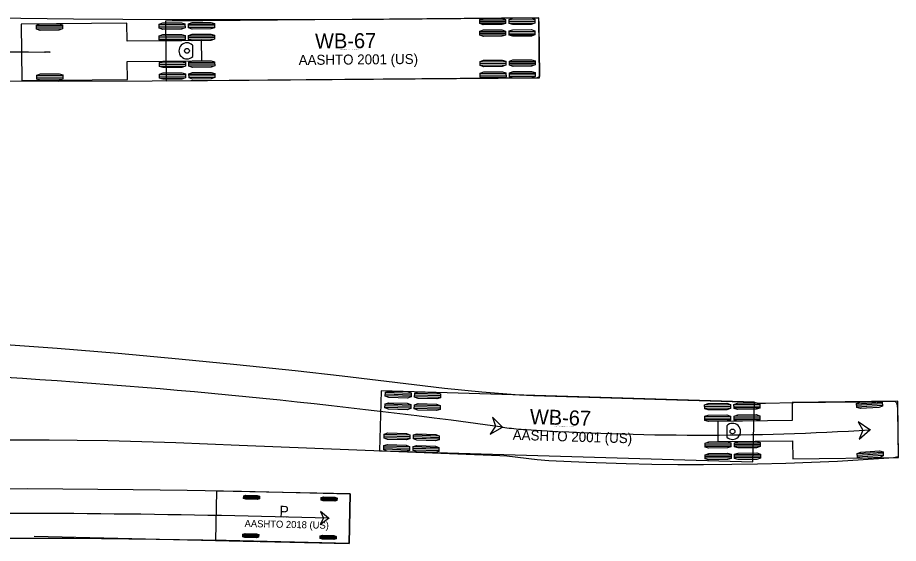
# Model space of a CAD drawing. Extents: x 2175591 to 2194071, y 76570 to 86955.
# Drawn here: x 2193090.5 to 2193215.5, y 86652.8 to 86727.4 of the extents above; entities that cross this region are included whole.
import ezdxf

# ---------------------------------------------------------------- set-up
doc = ezdxf.new("R2010")
doc.units = 0
doc.layers.add('C-UTIL-STRM-TEXT', color=7, linetype='Continuous')

msp = doc.modelspace()

# ---------------------------------------------------------------- linework, layer by layer
at = {"layer": 'C-UTIL-STRM-TEXT'}
for p, q in [((2193106.01, 86726.57), (2193091.01, 86726.44)), ((2193091.01, 86726.44), (2193091.08, 86718.44)), ((2193093.18, 86726.23), (2193096.85, 86726.26)), ((2193106.03, 86724), (2193106.01, 86726.57)), ((2193110.6, 86726.38), (2193114.26, 86726.41)), ((2193110.6, 86726.15), (2193114.26, 86726.18)), ((2193164.51, 86727.32), (2193111.51, 86726.86)), ((2193111.51, 86726.86), (2193111.58, 86718.37)), ((2193114.76, 86726.41), (2193118.43, 86726.44)), ((2193114.76, 86726.18), (2193118.43, 86726.22)), ((2193156.09, 86727.02), (2193159.76, 86727.05)), ((2193156.09, 86726.79), (2193159.76, 86726.82)), ((2193156.1, 86726.56), (2193159.76, 86726.59)), ((2193160.26, 86727.05), (2193163.92, 86727.08)), ((2193160.26, 86726.82), (2193163.93, 86726.85)), ((2193160.26, 86726.59), (2193163.93, 86726.63)), ((2193164.58, 86718.82), (2193164.51, 86727.32)), ((2193093.18, 86726), (2193096.85, 86726.03)), ((2193093.18, 86725.77), (2193096.85, 86725.8)), ((2193110.6, 86725.92), (2193114.27, 86725.95)), ((2193114.77, 86725.96), (2193118.43, 86725.99)), ((2193156.11, 86725.37), (2193159.77, 86725.4)), ((2193156.11, 86725.14), (2193159.77, 86725.17)), ((2193156.11, 86724.91), (2193159.78, 86724.94)), ((2193160.27, 86725.4), (2193163.94, 86725.43)), ((2193160.27, 86725.17), (2193163.94, 86725.2)), ((2193160.28, 86724.94), (2193163.94, 86724.98)), ((2193116.62, 86724.09), (2193106.03, 86724)), ((2193110.61, 86724.73), (2193114.28, 86724.76)), ((2193110.61, 86724.5), (2193114.28, 86724.53)), ((2193110.61, 86724.27), (2193114.28, 86724.3)), ((2193114.78, 86724.76), (2193118.44, 86724.79)), ((2193114.78, 86724.53), (2193118.44, 86724.57)), ((2193114.78, 86724.31), (2193118.45, 86724.34)), ((2193116.64, 86721.23), (2193116.62, 86724.09)), ((2193115.36, 86721.84), (2193115.35, 86723.46)), ((2193106.06, 86721.13), (2193116.64, 86721.23)), ((2193106.08, 86718.57), (2193106.06, 86721.13)), ((2193156.14, 86721.08), (2193159.81, 86721.11)), ((2193160.31, 86721.12), (2193163.98, 86721.15)), ((2193110.64, 86720.94), (2193114.31, 86720.98)), ((2193110.64, 86720.72), (2193114.31, 86720.75)), ((2193110.65, 86720.49), (2193114.31, 86720.52)), ((2193114.81, 86720.98), (2193118.47, 86721.01)), ((2193114.81, 86720.75), (2193118.48, 86720.78)), ((2193114.81, 86720.52), (2193118.48, 86720.55)), ((2193156.14, 86720.85), (2193159.81, 86720.89)), ((2193156.15, 86720.63), (2193159.81, 86720.66)), ((2193160.31, 86720.89), (2193163.98, 86720.92)), ((2193160.31, 86720.66), (2193163.98, 86720.69)), ((2193093.24, 86719.15), (2193096.91, 86719.18)), ((2193093.24, 86718.92), (2193096.91, 86718.95)), ((2193093.24, 86718.69), (2193096.91, 86718.72)), ((2193110.66, 86719.29), (2193114.32, 86719.33)), ((2193110.66, 86719.07), (2193114.32, 86719.1)), ((2193110.66, 86718.84), (2193114.33, 86718.87)), ((2193111.58, 86718.37), (2193164.58, 86718.82)), ((2193114.82, 86719.33), (2193118.49, 86719.36)), ((2193114.82, 86719.1), (2193118.49, 86719.13)), ((2193114.83, 86718.87), (2193118.49, 86718.9)), ((2193156.16, 86719.43), (2193159.82, 86719.46)), ((2193156.16, 86719.2), (2193159.82, 86719.24)), ((2193156.16, 86718.98), (2193159.83, 86719.01)), ((2193160.32, 86719.47), (2193163.99, 86719.5)), ((2193160.32, 86719.24), (2193163.99, 86719.27)), ((2193160.33, 86719.01), (2193163.99, 86719.04)), ((2193091.08, 86718.44), (2193106.08, 86718.57)), ((2193091.08, 86718.44), (2193091.08, 86718.44)), ((2193111.58, 86718.37), (2193111.58, 86718.37)), ((2193142.13, 86674.44), (2193141.88, 86665.94)), ((2193195.11, 86672.85), (2193142.13, 86674.44)), ((2193146.37, 86673.85), (2193142.7, 86673.96)), ((2193146.36, 86673.62), (2193142.7, 86673.73)), ((2193146.37, 86674.08), (2193142.71, 86674.19)), ((2193150.53, 86673.5), (2193146.86, 86673.61)), ((2193150.54, 86673.96), (2193146.87, 86674.07)), ((2193150.53, 86673.73), (2193146.87, 86673.84)), ((2193146.33, 86672.43), (2193142.66, 86672.54)), ((2193150.49, 86672.31), (2193146.83, 86672.42)), ((2193191.69, 86672.46), (2193188.02, 86672.42)), ((2193195.86, 86672.51), (2193192.19, 86672.47)), ((2193194.86, 86664.36), (2193195.11, 86672.85)), ((2193195.11, 86672.85), (2193195.11, 86672.85)), ((2193215.44, 86672.97), (2193200.44, 86672.79)), ((2193200.44, 86672.79), (2193200.47, 86670.23)), ((2193213.23, 86672.8), (2193209.57, 86672.57)), ((2193213.25, 86672.58), (2193209.59, 86672.35)), ((2193213.26, 86672.35), (2193209.6, 86672.12)), ((2193215.53, 86664.97), (2193215.44, 86672.97)), ((2193215.44, 86672.97), (2193215.44, 86672.97)), ((2193146.32, 86672.2), (2193142.65, 86672.31)), ((2193146.31, 86671.98), (2193142.65, 86672.08)), ((2193150.48, 86671.85), (2193146.81, 86671.96)), ((2193150.48, 86672.08), (2193146.82, 86672.19)), ((2193191.69, 86672.23), (2193188.03, 86672.19)), ((2193191.7, 86672), (2193188.03, 86671.96)), ((2193195.86, 86672.28), (2193192.19, 86672.24)), ((2193195.86, 86672.05), (2193192.2, 86672.01)), ((2193191.71, 86670.81), (2193188.04, 86670.77)), ((2193191.71, 86670.58), (2193188.05, 86670.54)), ((2193191.71, 86670.35), (2193188.05, 86670.31)), ((2193200.47, 86670.23), (2193189.88, 86670.1)), ((2193189.88, 86670.1), (2193189.92, 86667.24)), ((2193195.88, 86670.86), (2193192.21, 86670.82)), ((2193195.88, 86670.63), (2193192.21, 86670.59)), ((2193195.88, 86670.4), (2193192.21, 86670.36)), ((2193191.17, 86669.49), (2193191.19, 86667.88)), ((2193146.18, 86667.69), (2193142.52, 86667.8)), ((2193146.2, 86668.15), (2193142.53, 86668.26)), ((2193146.19, 86667.92), (2193142.53, 86668.03)), ((2193150.35, 86667.57), (2193146.68, 86667.68)), ((2193150.36, 86667.8), (2193146.69, 86667.91)), ((2193150.36, 86668.03), (2193146.7, 86668.14)), ((2193189.92, 86667.24), (2193200.5, 86667.36)), ((2193200.5, 86667.36), (2193200.53, 86664.79)), ((2193146.13, 86666.04), (2193142.47, 86666.15)), ((2193146.15, 86666.5), (2193142.48, 86666.61)), ((2193146.14, 86666.27), (2193142.48, 86666.38)), ((2193150.31, 86666.15), (2193146.64, 86666.26)), ((2193150.31, 86666.38), (2193146.65, 86666.49)), ((2193191.75, 86667.03), (2193188.09, 86666.99)), ((2193191.76, 86666.8), (2193188.09, 86666.76)), ((2193191.76, 86666.57), (2193188.09, 86666.53)), ((2193195.92, 86667.08), (2193192.25, 86667.03)), ((2193195.92, 86666.85), (2193192.26, 86666.81)), ((2193195.92, 86666.62), (2193192.26, 86666.58)), ((2193141.88, 86665.94), (2193194.86, 86664.36)), ((2193150.3, 86665.92), (2193146.63, 86666.03)), ((2193191.77, 86665.38), (2193188.11, 86665.34)), ((2193191.77, 86665.15), (2193188.11, 86665.11)), ((2193191.78, 86664.92), (2193188.11, 86664.88)), ((2193195.94, 86665.43), (2193192.27, 86665.38)), ((2193195.94, 86665.2), (2193192.27, 86665.16)), ((2193195.94, 86664.97), (2193192.28, 86664.93)), ((2193200.53, 86664.79), (2193215.53, 86664.97)), ((2193213.36, 86665.72), (2193209.7, 86665.5)), ((2193213.38, 86665.49), (2193209.72, 86665.27)), ((2193213.39, 86665.26), (2193209.73, 86665.04)), ((2193118.73, 86660.23), (2193118.57, 86653.23)), ((2193137.72, 86659.82), (2193118.73, 86660.23)), ((2193124.83, 86659.32), (2193122.58, 86659.36)), ((2193124.83, 86659.17), (2193122.58, 86659.22)), ((2193124.84, 86659.46), (2193122.59, 86659.51)), ((2193135.83, 86659.07), (2193133.58, 86659.13)), ((2193135.83, 86658.93), (2193133.58, 86658.99)), ((2193135.84, 86659.21), (2193133.59, 86659.27)), ((2193137.57, 86652.82), (2193137.72, 86659.82)), ((2193137.72, 86659.82), (2193137.72, 86659.82)), ((2193092.83, 86653.82), (2193124.51, 86653.08)), ((2193124.71, 86653.74), (2193122.46, 86653.79)), ((2193124.72, 86654.02), (2193122.47, 86654.07)), ((2193124.71, 86653.88), (2193122.47, 86653.93)), ((2193135.71, 86653.77), (2193133.46, 86653.84)), ((2193135.71, 86653.63), (2193133.46, 86653.7)), ((2193118.57, 86653.23), (2193137.57, 86652.82)), ((2193135.71, 86653.49), (2193133.46, 86653.56))]:
    msp.add_line(p, q, dxfattribs=at)
for points in [[(2193083.45, 86727.35), (2193098.45, 86727.16), (2193112.45, 86727.07), (2193127.11, 86727.07), (2193142.45, 86727.14), (2193164.44, 86727.32), (2193164.49, 86726.32), (2193164.52, 86722.99)], [(2193164.52, 86722.99), (2193164.56, 86718.99), (2193164.27, 86718.82), (2193109.61, 86718.35), (2193096.28, 86718.31), (2193085.95, 86718.36)], [(2193095.04, 86722.47), (2193094.71, 86722.47), (2193094.38, 86722.47)], [(2193088.15, 86681.05), (2193096.13, 86680.47), (2193104.76, 86679.77), (2193113.38, 86679), (2193121.64, 86678.19), (2193129.92, 86677.31), (2193136.55, 86676.56), (2193146.81, 86675.33), (2193151.11, 86674.84), (2193156.42, 86674.32), (2193161.73, 86673.87), (2193163.73, 86673.79), (2193195.04, 86672.85), (2193195.68, 86672.68), (2193196.68, 86672.68), (2193200.67, 86672.79), (2193209.67, 86672.9), (2193215.01, 86672.96), (2193215.25, 86672.73), (2193215.36, 86672.42), (2193215.41, 86671.75), (2193215.5, 86665.09), (2193214.85, 86664.94), (2193214.19, 86664.88), (2193210.53, 86664.64), (2193206.87, 86664.44), (2193203.21, 86664.28), (2193199.54, 86664.14), (2193195.55, 86664.04), (2193191.88, 86663.98), (2193187.88, 86663.96), (2193184.21, 86663.97), (2193180.55, 86664.01), (2193176.88, 86664.09), (2193171.22, 86664.29), (2193165.89, 86664.54), (2193164.23, 86664.68), (2193159.93, 86665.18), (2193158.93, 86665.24), (2193121.96, 86666.71), (2193112.97, 86667.05), (2193103.31, 86667.33), (2193098.97, 86667.41), (2193094.97, 86667.45), (2193089.31, 86667.43)], [(2193159.31, 86669.3), (2193157.9, 86670.72), (2193158.32, 86669.43), (2193157.57, 86668.31), (2193159.31, 86669.3)], [(2193211.48, 86668.92), (2193209.82, 86670.04), (2193210.48, 86668.86), (2193209.97, 86667.61), (2193211.48, 86668.92)], [(2193159.31, 86669.3), (2193159.64, 86669.25), (2193159.97, 86669.21), (2193160.3, 86669.17), (2193160.63, 86669.13), (2193160.96, 86669.09), (2193161.29, 86669.06), (2193161.62, 86669.03), (2193161.96, 86669), (2193162.29, 86668.98), (2193162.62, 86668.95)], [(2193075.89, 86660.56), (2193091.9, 86660.58), (2193106.91, 86660.47), (2193114.59, 86660.36), (2193122.26, 86660.21), (2193130.05, 86660.03), (2193137.71, 86659.82), (2193137.56, 86652.82), (2193120.11, 86653.2), (2193110.15, 86653.36), (2193098.52, 86653.49), (2193086.9, 86653.53)], [(2193134.65, 86656.38), (2193133.48, 86657.33), (2193133.9, 86656.4), (2193133.43, 86655.5), (2193134.65, 86656.38)]]:
    msp.add_lwpolyline(points, dxfattribs=at)
for points in [[(2193093.18, 86725.71), (2193093.18, 86726.29), (2193093.69, 86726.46), (2193096.33, 86726.49), (2193096.85, 86726.32), (2193096.85, 86725.75), (2193096.34, 86725.57), (2193093.7, 86725.55)], [(2193110.6, 86725.86), (2193110.59, 86726.43), (2193111.11, 86726.61), (2193113.75, 86726.63), (2193114.26, 86726.47), (2193114.27, 86725.89), (2193113.75, 86725.72), (2193111.11, 86725.69)], [(2193114.77, 86725.9), (2193114.76, 86726.47), (2193115.27, 86726.65), (2193117.91, 86726.67), (2193118.43, 86726.5), (2193118.43, 86725.93), (2193117.92, 86725.75), (2193115.28, 86725.73)], [(2193156.1, 86726.5), (2193156.09, 86727.07), (2193156.6, 86727.25), (2193159.24, 86727.27), (2193159.76, 86727.1), (2193159.76, 86726.53), (2193159.25, 86726.36), (2193156.61, 86726.33)], [(2193160.26, 86726.54), (2193160.26, 86727.11), (2193160.77, 86727.29), (2193163.41, 86727.31), (2193163.92, 86727.14), (2193163.93, 86726.57), (2193163.42, 86726.39), (2193160.78, 86726.37)], [(2193110.61, 86724.21), (2193110.61, 86724.78), (2193111.12, 86724.96), (2193113.76, 86724.98), (2193114.28, 86724.82), (2193114.28, 86724.24), (2193113.77, 86724.07), (2193111.13, 86724.04)], [(2193114.78, 86724.25), (2193114.78, 86724.82), (2193115.29, 86725), (2193117.93, 86725.02), (2193118.44, 86724.85), (2193118.45, 86724.28), (2193117.94, 86724.1), (2193115.3, 86724.08)], [(2193156.11, 86724.85), (2193156.11, 86725.42), (2193156.62, 86725.6), (2193159.26, 86725.62), (2193159.77, 86725.45), (2193159.78, 86724.88), (2193159.26, 86724.71), (2193156.62, 86724.68)], [(2193160.28, 86724.89), (2193160.27, 86725.46), (2193160.78, 86725.64), (2193163.42, 86725.66), (2193163.94, 86725.49), (2193163.94, 86724.92), (2193163.43, 86724.74), (2193160.79, 86724.72)], [(2193110.65, 86720.43), (2193110.64, 86721), (2193111.15, 86721.18), (2193113.79, 86721.2), (2193114.31, 86721.03), (2193114.31, 86720.46), (2193113.8, 86720.28), (2193111.16, 86720.26)], [(2193114.81, 86720.47), (2193114.81, 86721.04), (2193115.32, 86721.21), (2193117.96, 86721.24), (2193118.47, 86721.07), (2193118.48, 86720.5), (2193117.97, 86720.32), (2193115.33, 86720.3)], [(2193156.15, 86720.57), (2193156.14, 86721.14), (2193156.65, 86721.32), (2193159.29, 86721.34), (2193159.81, 86721.17), (2193159.81, 86720.6), (2193159.3, 86720.42), (2193156.66, 86720.4)], [(2193160.31, 86720.6), (2193160.31, 86721.18), (2193160.82, 86721.35), (2193163.46, 86721.38), (2193163.97, 86721.21), (2193163.98, 86720.64), (2193163.47, 86720.46), (2193160.83, 86720.44)], [(2193093.24, 86718.63), (2193093.24, 86719.2), (2193093.75, 86719.38), (2193096.39, 86719.4), (2193096.91, 86719.23), (2193096.91, 86718.66), (2193096.4, 86718.49), (2193093.76, 86718.46)], [(2193110.66, 86718.78), (2193110.66, 86719.35), (2193111.17, 86719.53), (2193113.81, 86719.55), (2193114.32, 86719.38), (2193114.33, 86718.81), (2193113.81, 86718.63), (2193111.18, 86718.61)], [(2193114.83, 86718.82), (2193114.82, 86719.39), (2193115.33, 86719.56), (2193117.97, 86719.59), (2193118.49, 86719.42), (2193118.49, 86718.85), (2193117.98, 86718.67), (2193115.34, 86718.65)], [(2193156.16, 86718.92), (2193156.16, 86719.49), (2193156.67, 86719.67), (2193159.31, 86719.69), (2193159.82, 86719.52), (2193159.83, 86718.95), (2193159.32, 86718.77), (2193156.68, 86718.75)], [(2193160.33, 86718.95), (2193160.32, 86719.53), (2193160.83, 86719.7), (2193163.47, 86719.73), (2193163.99, 86719.56), (2193163.99, 86718.99), (2193163.48, 86718.81), (2193160.84, 86718.79)], [(2193146.38, 86674.14), (2193146.36, 86673.57), (2193145.84, 86673.41), (2193143.2, 86673.49), (2193142.69, 86673.68), (2193142.71, 86674.25), (2193143.23, 86674.41), (2193145.87, 86674.33)], [(2193150.54, 86674.01), (2193150.52, 86673.44), (2193150.01, 86673.29), (2193147.37, 86673.36), (2193146.86, 86673.55), (2193146.88, 86674.12), (2193147.39, 86674.28), (2193150.03, 86674.2)], [(2193146.33, 86672.49), (2193146.31, 86671.92), (2193145.79, 86671.76), (2193143.15, 86671.84), (2193142.64, 86672.03), (2193142.66, 86672.6), (2193143.18, 86672.76), (2193145.82, 86672.68)], [(2193150.49, 86672.37), (2193150.47, 86671.79), (2193149.96, 86671.64), (2193147.32, 86671.72), (2193146.81, 86671.9), (2193146.83, 86672.48), (2193147.35, 86672.63), (2193149.98, 86672.55)], [(2193191.69, 86672.52), (2193191.7, 86671.95), (2193191.18, 86671.77), (2193188.55, 86671.74), (2193188.03, 86671.9), (2193188.02, 86672.48), (2193188.53, 86672.65), (2193191.17, 86672.69)], [(2193195.86, 86672.57), (2193195.86, 86672), (2193195.35, 86671.82), (2193192.71, 86671.79), (2193192.2, 86671.95), (2193192.19, 86672.52), (2193192.7, 86672.7), (2193195.34, 86672.73)], [(2193213.23, 86672.86), (2193213.27, 86672.29), (2193212.76, 86672.09), (2193210.13, 86671.92), (2193209.61, 86672.06), (2193209.57, 86672.63), (2193210.07, 86672.84), (2193212.71, 86673)], [(2193159.31, 86669.3), (2193157.9, 86670.72), (2193158.32, 86669.43), (2193157.57, 86668.31)], [(2193191.71, 86670.87), (2193191.72, 86670.3), (2193191.2, 86670.12), (2193188.56, 86670.09), (2193188.05, 86670.25), (2193188.04, 86670.83), (2193188.55, 86671), (2193191.19, 86671.04)], [(2193195.88, 86670.92), (2193195.88, 86670.35), (2193195.37, 86670.17), (2193192.73, 86670.14), (2193192.22, 86670.3), (2193192.21, 86670.87), (2193192.72, 86671.05), (2193195.36, 86671.08)], [(2193211.48, 86668.92), (2193209.82, 86670.04), (2193210.48, 86668.86), (2193209.97, 86667.61)], [(2193146.2, 86668.21), (2193146.18, 86667.64), (2193145.66, 86667.48), (2193143.02, 86667.56), (2193142.52, 86667.75), (2193142.53, 86668.32), (2193143.05, 86668.48), (2193145.69, 86668.4)], [(2193150.36, 86668.08), (2193150.35, 86667.51), (2193149.83, 86667.36), (2193147.19, 86667.43), (2193146.68, 86667.62), (2193146.7, 86668.19), (2193147.22, 86668.35), (2193149.86, 86668.27)], [(2193146.15, 86666.56), (2193146.13, 86665.99), (2193145.61, 86665.83), (2193142.98, 86665.91), (2193142.47, 86666.1), (2193142.48, 86666.67), (2193143, 86666.83), (2193145.64, 86666.75)], [(2193150.31, 86666.43), (2193150.3, 86665.86), (2193149.78, 86665.71), (2193147.14, 86665.79), (2193146.63, 86665.97), (2193146.65, 86666.54), (2193147.17, 86666.7), (2193149.81, 86666.62)], [(2193191.75, 86667.09), (2193191.76, 86666.51), (2193191.25, 86666.34), (2193188.61, 86666.31), (2193188.09, 86666.47), (2193188.09, 86667.04), (2193188.6, 86667.22), (2193191.24, 86667.25)], [(2193195.92, 86667.13), (2193195.93, 86666.56), (2193195.41, 86666.38), (2193192.77, 86666.35), (2193192.26, 86666.52), (2193192.25, 86667.09), (2193192.76, 86667.27), (2193195.4, 86667.3)], [(2193191.77, 86665.44), (2193191.78, 86664.86), (2193191.27, 86664.69), (2193188.63, 86664.66), (2193188.11, 86664.82), (2193188.11, 86665.39), (2193188.62, 86665.57), (2193191.26, 86665.6)], [(2193195.94, 86665.48), (2193195.94, 86664.91), (2193195.43, 86664.73), (2193192.79, 86664.7), (2193192.28, 86664.87), (2193192.27, 86665.44), (2193192.78, 86665.62), (2193195.42, 86665.65)], [(2193213.36, 86665.78), (2193213.39, 86665.21), (2193212.89, 86665), (2193210.26, 86664.84), (2193209.73, 86664.98), (2193209.7, 86665.55), (2193210.2, 86665.76), (2193212.84, 86665.92)], [(2193124.84, 86659.49), (2193124.83, 86659.14), (2193124.51, 86659.04), (2193122.89, 86659.08), (2193122.58, 86659.19), (2193122.59, 86659.54), (2193122.91, 86659.64), (2193124.52, 86659.6)], [(2193135.84, 86659.24), (2193135.83, 86658.89), (2193135.51, 86658.8), (2193133.89, 86658.84), (2193133.58, 86658.96), (2193133.59, 86659.31), (2193133.91, 86659.4), (2193135.53, 86659.36)], [(2193134.65, 86656.38), (2193133.48, 86657.33), (2193133.9, 86656.4), (2193133.43, 86655.5)], [(2193124.72, 86654.05), (2193124.71, 86653.7), (2193124.39, 86653.61), (2193122.77, 86653.64), (2193122.46, 86653.75), (2193122.47, 86654.1), (2193122.79, 86654.2), (2193124.41, 86654.17)], [(2193135.71, 86653.81), (2193135.7, 86653.46), (2193135.39, 86653.36), (2193133.77, 86653.41), (2193133.46, 86653.52), (2193133.47, 86653.87), (2193133.78, 86653.97), (2193135.4, 86653.92)]]:
    msp.add_lwpolyline(points, close=True, dxfattribs=at)
for centre, radius in [((2193094.38, 86722.47), 0.0417), ((2193094.38, 86722.47), 0.0417), ((2193095.04, 86722.47), 0.0417), ((2193114.54, 86722.64), 0.34), ((2193159.31, 86669.3), 0.0417), ((2193159.31, 86669.3), 0.0417), ((2193162.62, 86668.95), 0.0417), ((2193162.62, 86668.95), 0.0417), ((2193191.98, 86668.69), 0.34), ((2193211.48, 86668.92), 0.0417), ((2193134.65, 86656.38), 0.0417)]:
    msp.add_circle(centre, radius, dxfattribs=at)
for centre, radius, start, end in [((2193100.89, 88266.51), 1544.05, 266.96321, 269.75846), ((2193114.54, 86722.64), 1.14, 45.4894, 315.4894), ((2193030.16, 85731.9), 946.25, 82.15558, 86.89267), ((2193187.33, 87057.27), 389.1, 266.3593, 273.5588), ((2193191.98, 86668.69), 1.14, 225.6629, 135.6629), ((2193086.58, 84967.27), 1689.8, 88.36985, 90.43544)]:
    msp.add_arc(centre, radius, start, end, dxfattribs=at)

# ---------------------------------------------------------------- texts
for s, height, rotation, p in [('WB-67', 2.125, 0.4894, (2193132.73, 86722.97)), ('(c) 2024 Transoft Solutions, Inc. All rights reserved.', 0.085, 0.4894, (2193136.3, 86722.78)), ('AASHTO 2001 (US)', 1.4167, 0.4894, (2193130.4, 86720.64)), ('WB-67', 2.125, 358.2851, (2193163.19, 86669.73)), ('AASHTO 2001 (US)', 1.4167, 358.2851, (2193160.77, 86667.5)), ('(c) 2024 Transoft Solutions, Inc. All rights reserved.', 0.085, 358.2851, (2193166.75, 86669.41)), ('P', 1.5, 358.7485, (2193127.65, 86656.65)), ('AASHTO 2018 (US)', 1, 358.7485, (2193122.71, 86655.14)), ('(c) 2024 Transoft Solutions, Inc. All rights reserved.', 0.06, 358.7485, (2193126.92, 86656.52))]:
    msp.add_text(s, height=height, rotation=rotation, dxfattribs=at).set_placement(p)

doc.saveas('drawing.dxf')
